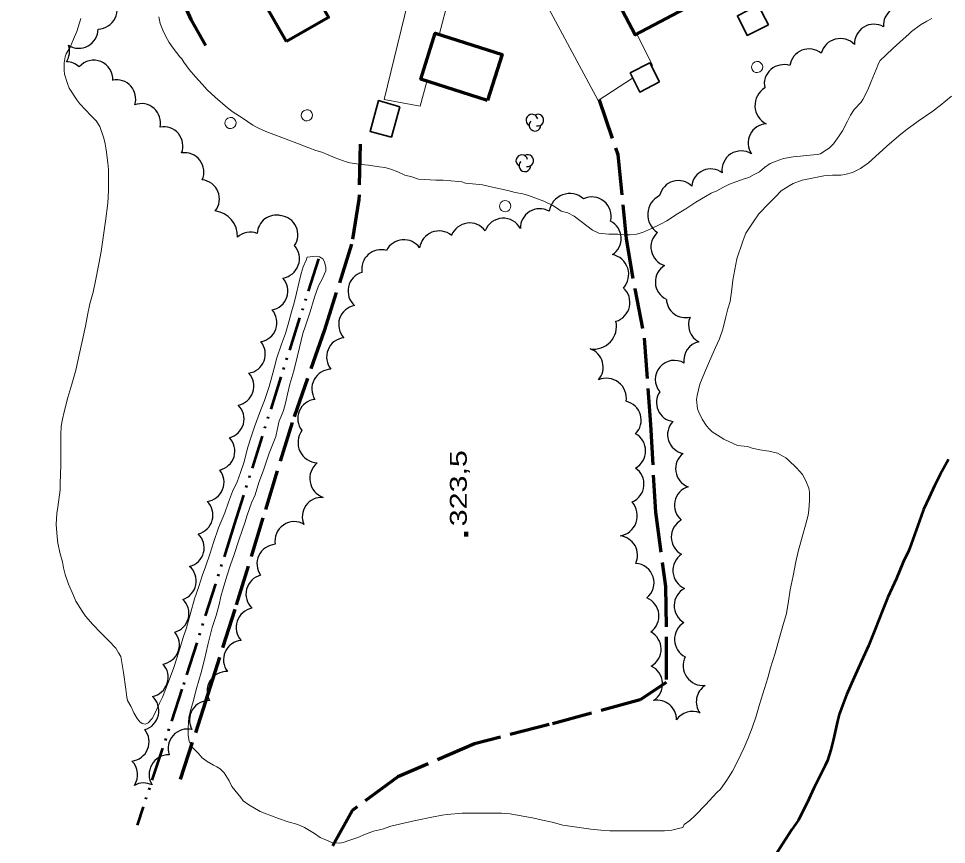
# Model space of a CAD drawing. Extents: x 240591 to 242335, y 5323482 to 5326937.
# Drawn here: x 241099.1 to 241264.3, y 5324410.4 to 5324557.4 of the extents above; entities that cross this region are included whole.
import ezdxf

# ---------------------------------------------------------------- set-up
doc = ezdxf.new("R2010")
doc.units = 0
doc.header["$LTSCALE"] = 1.2
doc.linetypes.add('DASH_DOUBLE_DOT', pattern=[9.2, 5, -1.2, 0.3, -1.2, 0.3, -1.2])
doc.linetypes.add('LONG_DASHED', pattern=[7.5, 6, -1.5])
for name, color, linetype, lineweight in [('1', 7, 'Continuous', 53), ('19', 7, 'Continuous', 13), ('2', 7, 'Continuous', 13), ('22', 7, 'LONG_DASHED', 70), ('3', 7, 'Continuous', 140), ('31', 7, 'Continuous', 70), ('36', 7, 'Continuous', 13), ('4', 7, 'DASH_DOUBLE_DOT', 53), ('44', 7, 'Continuous', 25)]:
    doc.layers.add(name, color=color, linetype=linetype, lineweight=lineweight)

msp = doc.modelspace()

# ---------------------------------------------------------------- linework, layer by layer
at = {"layer": '1', "linetype": 'LONG_DASHED'}
msp.add_lwpolyline([(241264.7, 5324478.9), (241263.2, 5324476.2), (241262.2, 5324474.2), (241261.2, 5324472.1), (241260.2, 5324470), (241259.8, 5324468.8), (241258.9, 5324466.3), (241258, 5324463.8), (241257.6, 5324462.7), (241256.6, 5324460.6), (241255.4, 5324457.7), (241253.9, 5324454.4), (241252.9, 5324452), (241251.6, 5324448.7), (241250.4, 5324445.7), (241249.2, 5324443), (241247.9, 5324440.1), (241246.5, 5324437), (241245.6, 5324434.6), (241245.2, 5324433.5), (241244.9, 5324432.3), (241244.2, 5324429.1), (241243.7, 5324427.2), (241243.1, 5324425.3), (241242.7, 5324424.4), (241241.7, 5324422.4), (241240.7, 5324420.4), (241239.8, 5324418.4), (241238.4, 5324415.5), (241237.9, 5324414.6), (241236.8, 5324413), (241235.2, 5324410.5), (241233.5, 5324407.9)], dxfattribs=at)
at = {"layer": '19'}
msp.add_line((241174, 5324554.5), (241176.3, 5324563.2), dxfattribs=at)
for points in [[(241169.6, 5324565.2), (241164.2, 5324543), (241170.6, 5324541.8), (241171.8, 5324546.2)], [(241190.5, 5324564.8), (241202.3, 5324542.8), (241208.4, 5324546.8)], [(241211.8, 5324549), (241212, 5324549.1), (241209.1, 5324554.7)]]:
    msp.add_lwpolyline(points, dxfattribs=at)
at = {"layer": '2', "linetype": 'LONG_DASHED'}
for points in [[(241118.4, 5324436.6), (241118.2, 5324438), (241117.8, 5324441), (241117.3, 5324443.8), (241116.9, 5324444.5), (241116.4, 5324445.3), (241115.2, 5324446.6), (241113.7, 5324448.1), (241112.3, 5324449.5), (241111, 5324451), (241110.4, 5324451.9), (241109.3, 5324453.7), (241108.9, 5324454.7), (241108, 5324456.7), (241107.4, 5324458.4), (241107.1, 5324459.6), (241106.9, 5324460.7), (241106.5, 5324462.1), (241106.1, 5324464), (241106, 5324465.1), (241105.8, 5324467.3), (241105.9, 5324469.3), (241106.1, 5324470.4), (241106.5, 5324473.5), (241106.5, 5324474.6), (241106.6, 5324477.9), (241106.6, 5324480.5), (241106.6, 5324483.3), (241106.7, 5324484.8), (241106.9, 5324486.1), (241107.2, 5324487.4), (241107.9, 5324489.9), (241108.6, 5324492.3), (241109.3, 5324494.8), (241109.9, 5324497.5), (241110.5, 5324500.2), (241111, 5324502.6), (241111.4, 5324504.6), (241111.8, 5324506.6), (241112.4, 5324508.7), (241112.8, 5324510.7), (241113.4, 5324513.7), (241113.8, 5324515.9), (241114.1, 5324518), (241114.6, 5324521.3), (241115, 5324524.5), (241115.1, 5324526.8), (241115.1, 5324528), (241115.1, 5324530.5), (241115, 5324531.7), (241114.7, 5324534), (241114.5, 5324535.1), (241114.3, 5324536.1), (241113.6, 5324538.2), (241112.9, 5324539.2), (241112, 5324540.1), (241110, 5324542.2), (241109.5, 5324542.9), (241108.1, 5324545), (241107.8, 5324545.8), (241107.3, 5324547.5), (241107.2, 5324548.2), (241107.2, 5324549.5), (241107.4, 5324550.6), (241107.6, 5324551.1), (241108.3, 5324552.3), (241108.9, 5324553.7), (241109.5, 5324555.1), (241110.2, 5324557.4)], [(241265.2, 5324543.6), (241263.2, 5324541.9), (241261.7, 5324540.8), (241259.3, 5324539.1), (241257.1, 5324537.5), (241255.8, 5324536.5), (241253.7, 5324534.7), (241252.3, 5324533.4), (241250.4, 5324531.7), (241249, 5324530.7), (241247.6, 5324530), (241246.2, 5324529.6), (241245.5, 5324529.5), (241244, 5324529.5), (241242.5, 5324529.4), (241241, 5324529.1), (241238.6, 5324528.6), (241237, 5324528), (241236.3, 5324527.6), (241234.9, 5324526.7), (241233.8, 5324525.6), (241232.6, 5324524.4), (241230.9, 5324522.6), (241230, 5324521.3), (241228.6, 5324519.2), (241228.3, 5324518.4), (241228, 5324517.6), (241227, 5324514.6), (241226.6, 5324512.7), (241226.3, 5324510.8), (241226.1, 5324509.2), (241225.8, 5324507), (241225.4, 5324505.7), (241225, 5324504.3), (241224.5, 5324502.1), (241223.9, 5324500.4), (241223.2, 5324498.8), (241222.1, 5324496.4), (241221.2, 5324494.3), (241220.4, 5324492.3), (241219.9, 5324490.3), (241219.8, 5324489.6), (241220, 5324487.9), (241220.2, 5324487.3), (241220.8, 5324486.1)], [(241220.8, 5324486.1), (241221.6, 5324484.9), (241222.1, 5324484.3), (241222.6, 5324483.8), (241224, 5324482.9), (241224.7, 5324482.5), (241227.1, 5324481.4), (241227.7, 5324481.3), (241228.9, 5324481.2), (241229.7, 5324480.9), (241231.1, 5324480.6), (241232.7, 5324480.4), (241234.2, 5324480), (241235.3, 5324479.4), (241235.7, 5324479.2), (241236.2, 5324478.8), (241237.6, 5324477.4), (241238.7, 5324476.2), (241239.3, 5324475.1), (241239.8, 5324473.8), (241239.9, 5324473.1), (241239.9, 5324471.6), (241239.8, 5324469.9), (241239.7, 5324469), (241239.2, 5324467.2), (241238.7, 5324465.3), (241237.9, 5324462.5), (241237.5, 5324460.7), (241237, 5324458.2), (241236.5, 5324455.7), (241236.2, 5324453.7), (241235.8, 5324451.5), (241235.2, 5324449.3), (241234.6, 5324447.2), (241233.8, 5324444.4), (241233, 5324441.8), (241232.5, 5324440), (241231.6, 5324437.2), (241231, 5324435.3), (241230.4, 5324433.2), (241229.7, 5324431.1), (241229, 5324429.3), (241228.3, 5324427.6), (241227.1, 5324425.1), (241226.2, 5324423.4), (241225.2, 5324421.8), (241224.1, 5324420.2), (241223.4, 5324419.6), (241221.4, 5324417.4), (241219.6, 5324415.6), (241218.6, 5324414.6), (241217.6, 5324413.9), (241217.4, 5324413.4), (241216.6, 5324413.2), (241215.4, 5324412.9), (241214.1, 5324412.8), (241212.8, 5324412.8), (241210.2, 5324412.8), (241207, 5324412.8), (241204.4, 5324412.8), (241202.8, 5324412.9), (241201, 5324413.1), (241198.1, 5324413.5), (241196, 5324413.8), (241194.1, 5324414.3), (241192.4, 5324414.7), (241190.6, 5324415.1), (241188.9, 5324415.4), (241186.6, 5324415.8), (241185.1, 5324415.9), (241183.5, 5324415.9), (241180.9, 5324415.9), (241178.1, 5324415.9), (241175.4, 5324415.7), (241174.5, 5324415.6), (241172.7, 5324415.2), (241169.8, 5324414.6), (241166.9, 5324414), (241165.4, 5324413.6), (241163.9, 5324413.1), (241162.3, 5324412.7), (241160.9, 5324412.2), (241159.5, 5324411.6), (241158.1, 5324411.1), (241156.9, 5324410.7), (241156.3, 5324410.6), (241154.9, 5324410.7), (241153.9, 5324411.1), (241152.8, 5324411.6), (241151.8, 5324412.3), (241150, 5324413.4), (241148.8, 5324413.9), (241147.1, 5324414.4), (241145.4, 5324415), (241142.9, 5324415.9), (241142.1, 5324416.2), (241140.8, 5324417), (241140.1, 5324417.4)]]:
    msp.add_lwpolyline(points, dxfattribs=at)
at = {"layer": '2'}
for points in [[(241207.9, 5324518.9), (241206.9, 5324518.9), (241205.8, 5324519), (241204.2, 5324519), (241202.9, 5324519.1), (241202.4, 5324519.2), (241201.3, 5324519.7), (241200.3, 5324520.5), (241198, 5324522.2), (241196.9, 5324522.8), (241195.7, 5324523.1), (241194.9, 5324523.7), (241194.2, 5324524.1), (241192.6, 5324524.9), (241191.5, 5324525.3), (241189.9, 5324525.9), (241188.9, 5324526.2), (241187.5, 5324526.4), (241186.2, 5324526.8), (241183.5, 5324527.4), (241181.7, 5324527.8), (241180.5, 5324527.9), (241178.7, 5324528.1), (241178, 5324528.3), (241177.4, 5324528.4), (241174.7, 5324528.6), (241173.4, 5324528.6), (241170.3, 5324528.8), (241169.1, 5324529.2), (241167.9, 5324529.5), (241166.6, 5324530.1), (241165.4, 5324530.6), (241164.3, 5324530.9), (241163.3, 5324531), (241161.4, 5324531.3), (241160.1, 5324531.4), (241158.1, 5324531.7), (241157.4, 5324531.9), (241155.5, 5324532.6), (241154.2, 5324533.1), (241153.1, 5324533.6), (241152, 5324533.9), (241150.8, 5324534.4), (241148.2, 5324535.4), (241145.5, 5324536.4), (241143.1, 5324537.3), (241141.8, 5324537.9), (241140.8, 5324538.4), (241138.9, 5324539.7), (241137.3, 5324540.7), (241136.3, 5324541.5), (241134.1, 5324543.4), (241132.7, 5324544.7), (241131.8, 5324545.7), (241130.6, 5324547), (241129.5, 5324548.3), (241128.5, 5324549.6), (241128.2, 5324550.2), (241127.8, 5324550.6), (241126.6, 5324552.1), (241125.9, 5324553.1), (241125.3, 5324554.2), (241124.8, 5324555.3), (241124.3, 5324556.5), (241124.1, 5324557.7)], [(241261.7, 5324557.4), (241260.8, 5324556.9), (241259.7, 5324556.3), (241258.1, 5324555.1), (241257.6, 5324554.6), (241256.6, 5324553.7), (241254.8, 5324552.1), (241253.5, 5324550.9), (241252.5, 5324549.9), (241252.2, 5324549.4), (241251.8, 5324548.3), (241250.9, 5324546.2), (241250.3, 5324544.7), (241249.4, 5324543), (241249.1, 5324542.5), (241247.9, 5324541.2), (241247.2, 5324540.2), (241246.7, 5324539.1), (241245.8, 5324537.4), (241245.2, 5324536.5), (241244.2, 5324535.1), (241243.4, 5324534.3), (241242.5, 5324533.7), (241241.9, 5324533.3), (241241.3, 5324533.2), (241239.4, 5324533), (241238.3, 5324532.9), (241237, 5324532.8), (241235.3, 5324532.5), (241234, 5324532), (241232.9, 5324531.6), (241231.9, 5324530.9), (241231, 5324530.1), (241230.1, 5324529.6), (241229.1, 5324529.1), (241228.1, 5324528.8), (241225.7, 5324527.9), (241224.5, 5324527.3), (241223.4, 5324526.7), (241222.4, 5324526.3), (241221.4, 5324525.7), (241219.7, 5324524.7), (241218.8, 5324524.1), (241217.9, 5324523.5), (241216.4, 5324522.6), (241214.5, 5324521.4), (241213.4, 5324520.8), (241211.8, 5324520), (241210.2, 5324519.3), (241209.1, 5324519), (241207.9, 5324518.9)], [(241140.1, 5324417.4), (241139.1, 5324418.1), (241138.7, 5324418.7), (241137.1, 5324420.7), (241136.6, 5324421.7), (241135.7, 5324423.1), (241135, 5324423.8), (241134.4, 5324424.2), (241133.8, 5324424.5), (241132.7, 5324425.1), (241131.8, 5324425.8), (241131.1, 5324426.6), (241130, 5324427.7), (241129.5, 5324428.7), (241129.3, 5324429.8), (241129.3, 5324431.1), (241129.4, 5324433), (241129.7, 5324434.2), (241130.1, 5324435.6), (241130.8, 5324438.1), (241131.6, 5324441), (241132.2, 5324443.3), (241132.8, 5324445.9), (241133.6, 5324449), (241134.3, 5324451.1), (241134.8, 5324453.1), (241135.1, 5324454.5), (241135.5, 5324455.9), (241136.2, 5324458.1), (241136.9, 5324460.3), (241137.4, 5324461.8), (241138.4, 5324464.7), (241139.4, 5324467.6), (241139.8, 5324469), (241140.6, 5324471.2), (241141.2, 5324472.6), (241141.9, 5324474.8), (241142.7, 5324477), (241143.7, 5324480), (241144.3, 5324481.5), (241144.9, 5324483), (241145.2, 5324484.4), (241145.5, 5324485.8), (241145.8, 5324486.4), (241146.3, 5324487.6), (241146.6, 5324488.9), (241147, 5324490.5), (241147.4, 5324492.3), (241148.1, 5324494.7), (241148.7, 5324497.1), (241149.1, 5324498.8), (241149.7, 5324501.3), (241150.2, 5324502.7), (241151, 5324505.2), (241151.8, 5324507.8), (241152.5, 5324509.8), (241153.1, 5324510.9), (241153.8, 5324512.5), (241153.8, 5324513.1), (241153.6, 5324514.1), (241153.3, 5324514.6), (241152.7, 5324515), (241152, 5324515.1), (241150.5, 5324514.9), (241150.3, 5324514.4), (241149.8, 5324513.2), (241149.4, 5324512), (241149, 5324510.3), (241148.6, 5324508.5), (241148.2, 5324506.8), (241147.7, 5324505.2), (241147.2, 5324503.4), (241146.6, 5324501.3), (241145.9, 5324499.4), (241145, 5324496.8), (241144.8, 5324495.8), (241144.2, 5324493.6), (241143.7, 5324491.9), (241142.9, 5324489.4), (241142.2, 5324487.6), (241141.1, 5324484.7), (241140.5, 5324482.9), (241139.9, 5324481.1), (241139.2, 5324478.3), (241138.6, 5324476.6), (241138, 5324474.9), (241137.2, 5324473.2), (241136.5, 5324471.3), (241135.8, 5324469.4), (241134.7, 5324466.7), (241133.8, 5324464.1), (241133.2, 5324462.2), (241132.4, 5324459.8), (241131.8, 5324458.2), (241131.2, 5324456.3), (241130.4, 5324454.1), (241129.8, 5324451.7), (241129, 5324448.9), (241128.4, 5324447.2), (241128.1, 5324446.2), (241127.3, 5324443.5)], [(241127.3, 5324443.5), (241126.7, 5324441.7), (241125.7, 5324439), (241124.7, 5324436.6), (241124.2, 5324435.5), (241123.5, 5324433.9), (241122.9, 5324432.8), (241122.2, 5324432), (241121.7, 5324431.8), (241121.1, 5324431.9), (241120.7, 5324432.2), (241120.2, 5324432.8), (241119.6, 5324433.8), (241119.1, 5324435), (241118.5, 5324436), (241118.4, 5324436.6)]]:
    msp.add_lwpolyline(points, dxfattribs=at)
at = {"layer": '22'}
for points in [[(241099.1, 5324625), (241104.6, 5324618.2), (241108.4, 5324609), (241110.8, 5324597.7), (241114.5, 5324587.5), (241118.2, 5324580.3), (241122.7, 5324574.8), (241125.5, 5324568.3), (241127.5, 5324562.3), (241129.8, 5324557.2), (241132.4, 5324552.6)], [(241202.5, 5324542.9), (241205.8, 5324533.2), (241207.3, 5324518.2), (241208.8, 5324509.3), (241210.5, 5324500.5), (241211.6, 5324485.1), (241212.5, 5324469.5), (241214.3, 5324456.3), (241214.4, 5324446.9), (241214.4, 5324439.2), (241209.8, 5324436.1), (241193.6, 5324431.7), (241180.3, 5324428.3), (241166.6, 5324422.4), (241158.5, 5324416.4), (241154, 5324408.4)], [(241159.9, 5324535), (241159.7, 5324525.2), (241158.4, 5324517.2), (241153.5, 5324501.8), (241147.8, 5324485.5), (241142.6, 5324468.5), (241137.6, 5324452.2), (241132.8, 5324437.1), (241127.9, 5324421.9)]]:
    msp.add_lwpolyline(points, dxfattribs=at)
at = {"layer": '3'}
msp.add_line((241178.8, 5324465.2), (241178.8, 5324466), dxfattribs=at)
at = {"layer": '31'}
for points in [[(241146.8, 5324553.3), (241140.8, 5324563.8), (241148.3, 5324568.1), (241154.3, 5324557.6)], [(241219.9, 5324560.3), (241208.9, 5324554.5), (241204.9, 5324562.1), (241215.9, 5324567.9)], [(241182.6, 5324542.8), (241170.7, 5324546.6), (241173.3, 5324554.8), (241185.2, 5324551)]]:
    msp.add_lwpolyline(points, close=True, dxfattribs=at)
at = {"layer": '31', "lineweight": 35}
for points in [[(241232.6, 5324556.3), (241228.8, 5324554.4), (241227.1, 5324557.9), (241230.8, 5324559.8)], [(241213.2, 5324546.1), (241209.7, 5324544.3), (241208, 5324547.7), (241211.5, 5324549.5)], [(241167, 5324541.7), (241165.5, 5324536.3), (241161.7, 5324537.3), (241163.2, 5324542.8)]]:
    msp.add_lwpolyline(points, close=True, dxfattribs=at)
at = {"layer": '36'}
for centre in [(241230.59, 5324548.763), (241150.42, 5324540.163), (241136.85, 5324538.793), (241185.73, 5324523.993)]:
    msp.add_ellipse(centre, major_axis=(-0.463, 0.886), ratio=0.999959, dxfattribs=at)
at = {"layer": '4'}
msp.add_lwpolyline([(241152.5, 5324514.6), (241145.8, 5324493.6), (241137.5, 5324467.3), (241128.2, 5324438), (241120.2, 5324413.8)], dxfattribs=at)
at = {"layer": '44'}
for centre, radius, start, end in [((241256.529, 5324556.208), 3.44, 67.9901, 184.63178), ((241251.391, 5324552.917), 3.464, 60.43923, 182.59009), ((241245.407, 5324550.336), 3.498, 43.85823, 165.53343), ((241239.837, 5324548.543), 3.446, 50.69618, 172.27603), ((241235.32, 5324545.743), 3.445, 71.3457, 191.94286), ((241232.432, 5324535.229), 3.437, 93.37158, 213.77933), ((241128.643, 5324530.055), 3.453, 336.53106, 98.53672), ((241131.441, 5324525.273), 3.427, 321.707, 83.812), ((241179.421, 5324517.537), 3.465, 36.95244, 158.79942), ((241173.968, 5324516.098), 3.49, 50.46188, 172.23371), ((241137.558, 5324491.931), 3.433, 280.94546, 42.7283), ((241135.806, 5324486.106), 3.436, 283.88374, 45.58927), ((241134.169, 5324480.374), 3.435, 282.45454, 44.23841), ((241132.245, 5324474.849), 3.438, 277.43562, 39.17417), ((241219.347, 5324470.737), 3.465, 107.58306, 229.57457), ((241205.597, 5324468.905), 3.676, 279.59184, 41.28059), ((241145.029, 5324460.318), 3.481, 93.94091, 215.62675), ((241124.279, 5324445.899), 3.461, 278.98895, 40.78587)]:
    msp.add_arc(centre, radius, start, end, dxfattribs=at)
for centre, major_axis, ratio, start_param, end_param in [((241113.124, 5324559.062), (3.178, -1.599), 0.998984, 5.2192653, 7.3433657), ((241109.817, 5324555.554), (1.425, -3.148), 0.999268, 5.2968221, 7.4163795), ((241104.762, 5324551.517), (2.309, 2.502), 0.999938, 4.889501, 5.7907901), ((241112.489, 5324546.559), (-0.95, 3.276), 0.999594, 4.3799134, 6.8567821), ((241107.608, 5324546.296), (-3.317, -0.748), 0.999984, 3.7437601, 4.4833547), ((241116.552, 5324543.099), (0.151, 3.402), 0.999403, 4.4438226, 6.5252261), ((241233.867, 5324541.923), (1.986, -3.063), 0.999995, 3.1192134, 5.2429349), ((241120.934, 5324538.801), (2.43, 2.445), 0.998991, 5.2803101, 7.4044218), ((241190.51, 5324539.297), (-0.48, 0.93), 0.99996, 4.461003, 8.4308781), ((241191.556, 5324539.309), (-0.48, 0.93), 0.99996, 2.4480745, 6.3346498), ((241191.043, 5324538.404), (-0.48, 0.93), 0.99996, 0.3044344, 4.2434434), ((241124.942, 5324534.71), (2.627, 2.191), 0.999994, 5.2170457, 7.3477437), ((241227.778, 5324530.396), (-1.888, 2.874), 0.999951, 5.1506746, 7.4059446), ((241188.71, 5324532.087), (-0.48, 0.93), 0.99996, 4.461003, 8.4308781), ((241189.756, 5324532.099), (-0.48, 0.93), 0.99996, 2.4480745, 6.3346498), ((241189.243, 5324531.194), (-0.48, 0.93), 0.99996, 0.3044344, 4.2434434), ((241222.332, 5324527.249), (-1.361, 3.091), 0.999306, 5.2199407, 7.3472488), ((241216.575, 5324525.12), (-0.451, 3.389), 0.999826, 5.3747436, 7.5004911), ((241197.233, 5324522.505), (-1.266, 3.505), 0.998792, 5.2188943, 7.3445872), ((241201.164, 5324522.185), (-2.788, 2.05), 0.99926, 3.521943, 5.7895422), ((241214.887, 5324522.487), (-3.652, 0.91), 0.999903, 5.4095736, 7.5323854), ((241191.881, 5324520.139), (-3.337, -0.805), 0.989161, 3.9667027, 6.0866581), ((241133.463, 5324518.572), (4.329, 1.634), 0.99985, 5.8978155, 7.3483093), ((241144.985, 5324518.992), (-1.645, 2.98), 0.997412, 5.5365601, 7.308944), ((241145.43, 5324518.908), (-1.543, 3.042), 0.999751, 3.6350788, 5.7152941), ((241185.406, 5324518.442), (-3.397, -0.471), 0.994479, 3.476783, 5.7920063), ((241202.934, 5324518.26), (-2.951, 1.815), 0.992301, 2.6959679, 4.7886699), ((241140.386, 5324515.955), (-2.81, -1.924), 0.999984, 3.749741, 4.8562594), ((241215.14, 5324516.716), (-3.369, -0.73), 0.999994, 5.2177053, 7.3432352), ((241167.701, 5324514.595), (-3.413, -0.415), 0.995027, 3.6354874, 5.7066659), ((241145.605, 5324514.637), (-0.67, 3.44), 0.999995, 3.1138674, 5.2443829), ((241163.597, 5324512.842), (-2.681, -2.131), 0.988824, 3.7401753, 5.7928911), ((241204.148, 5324511.841), (3.401, 1.131), 0.99949, 5.2203674, 7.3446918), ((241161.169, 5324508.904), (-0.745, -3.36), 0.990331, 3.6378349, 5.786943), ((241215.872, 5324510.502), (0.156, -3.395), 0.999751, 3.6337627, 5.7910154), ((241143.629, 5324508.892), (3.255, -1.091), 0.997773, 5.2142474, 7.3388305), ((241204.464, 5324506.829), (3.408, -0.75), 0.99715, 5.2147334, 7.3402957), ((241217.835, 5324507.544), (-1.613, -2.993), 0.99995, 5.2506384, 7.0245331), ((241159.553, 5324502.892), (0.71, -3.391), 0.999995, 3.115959, 5.2443148), ((241141.663, 5324503.254), (3.239, -1.138), 0.999328, 5.2159278, 7.3426244), ((241221.77, 5324502.869), (2.107, -2.666), 0.999731, 3.6259558, 5.1475143), ((241201.535, 5324502.567), (2.714, -2.968), 0.999996, 5.373296, 7.3446681), ((241139.606, 5324497.659), (3.204, -1.229), 0.999994, 5.2173512, 7.3497892), ((241157.408, 5324497.127), (-3.209, 1.29), 0.999951, 5.2155643, 7.3459522), ((241220.945, 5324496.507), (0.855, -3.295), 0.999707, 3.0956856, 4.5929027), ((241199.729, 5324495.331), (-2.673, 2.199), 0.999995, 3.1182765, 5.0685839), ((241215.859, 5324493.143), (-3.383, -0.329), 0.999655, 4.0743367, 6.8928355), ((241154.785, 5324491.481), (-3.067, 1.626), 0.999342, 5.2184325, 7.3439614), ((241203.753, 5324489.789), (2.188, 2.82), 0.999584, 5.220305, 7.3473318), ((241216.083, 5324489.027), (1.135, -3.201), 0.999859, 3.773263, 5.790564), ((241152.257, 5324486.168), (-3.188, 1.34), 0.998219, 5.2218168, 7.3422197), ((241206.513, 5324485.893), (3.305, 0.972), 0.999333, 5.2163225, 7.3436769), ((241218.085, 5324483.336), (-3.266, -1.053), 0.9998, 5.223203, 7.3471019), ((241152.519, 5324481.928), (3.035, -2.056), 0.999995, 3.1195676, 5.2427442), ((241207.256, 5324480.42), (3.307, -1.127), 0.999963, 5.5501983, 7.6730283), ((241219.517, 5324477.251), (3.201, -1.244), 0.999983, 2.5984865, 4.7207719), ((241154.501, 5324475.499), (-3.5, -0.603), 0.999746, 5.2174062, 7.3445206), ((241206.986, 5324474.516), (3.453, -0.349), 0.999561, 5.219999, 7.3499062), ((241130.276, 5324468.997), (3.314, -0.916), 0.99858, 5.2207359, 7.3449928), ((241153.053, 5324468.741), (-2.783, -2.033), 0.986472, 4.0099652, 6.0749685), ((241148.168, 5324464.412), (-2.69, -2.149), 0.989541, 3.4906805, 5.7867795), ((241218.805, 5324465.061), (1.776, -2.999), 0.999995, 3.1182017, 5.2439514), ((241128.708, 5324463.187), (3.24, -1.142), 0.999384, 5.3015838, 7.4265714), ((241205.861, 5324461.843), (-1.317, 3.196), 0.997822, 3.8890094, 5.7900909), ((241219.103, 5324459.132), (-3.483, -0.323), 0.998947, 5.22278, 7.3427198), ((241127.322, 5324457.263), (3.241, -1.118), 0.999761, 5.3459327, 7.4750809), ((241208.795, 5324456.945), (-0.636, 3.4), 0.997448, 3.6346237, 6.0400674), ((241143.065, 5324454.922), (-2.904, 1.913), 0.999962, 5.5461038, 7.6727768), ((241219.317, 5324452.861), (-3.467, 0.379), 0.99951, 5.3098365, 7.4347363), ((241125.992, 5324451.477), (-2.493, 2.369), 0.999983, 2.5979028, 4.72061), ((241209.631, 5324451.019), (3.469, 0.409), 0.999995, 5.221804, 7.3462119), ((241141.285, 5324449.014), (-2.925, 1.835), 0.999929, 5.4545509, 7.5858143), ((241219.377, 5324446.872), (-3.486, 0.165), 0.999511, 5.3074215, 7.4325013), ((241210.028, 5324445.128), (3.479, -0.145), 0.998861, 5.2746619, 7.4013916), ((241139.063, 5324443.225), (-2.92, 1.875), 0.999831, 5.3763292, 7.49875), ((241220.99, 5324442.196), (-2.921, -2.025), 0.99958, 5.2209547, 7.3464745), ((241122.27, 5324440.125), (3.3, -1.074), 0.999995, 5.2212563, 7.3434051), ((241136.134, 5324437.679), (-2.954, 1.811), 0.999864, 5.2173093, 7.349006), ((241210.266, 5324438.931), (-1.982, 2.899), 0.999995, 3.1149, 5.2440744), ((241223.215, 5324435.757), (0.69, -3.387), 0.99759, 3.51493, 5.1319015), ((241120.612, 5324434.139), (-1.046, 3.315), 0.999995, 3.1180917, 5.2438704), ((241212.808, 5324432.585), (-2.419, 2.469), 0.997794, 3.9210288, 5.6926754), ((241132.989, 5324432.514), (-2.961, 1.792), 0.998769, 5.2183436, 7.3432621), ((241219.089, 5324430.572), (-3.453, -0.25), 0.99994, 4.2419982, 5.6064378), ((241118.881, 5324428.636), (3.198, -1.318), 0.999995, 5.2189521, 7.3498246), ((241129.176, 5324427.434), (-1.945, 2.874), 0.99993, 5.4543881, 7.5857206), ((241125.869, 5324422.795), (-2.854, 2.069), 0.9997, 5.3336596, 7.4582492), ((241116.882, 5324422.752), (1.23, 3.205), 0.989247, 4.4978907, 5.8706395), ((241121.335, 5324417.883), (-2.801, -2), 0.989584, 3.6365478, 4.5882212)]:
    msp.add_ellipse(centre, major_axis=major_axis, ratio=ratio, start_param=start_param, end_param=end_param, dxfattribs=at)

# ---------------------------------------------------------------- texts
at = {"layer": '3', "width": 1.35}
msp.add_text('323,5', height=3, rotation=90, dxfattribs=at).set_placement((241178.9, 5324467))

doc.saveas('drawing.dxf')
